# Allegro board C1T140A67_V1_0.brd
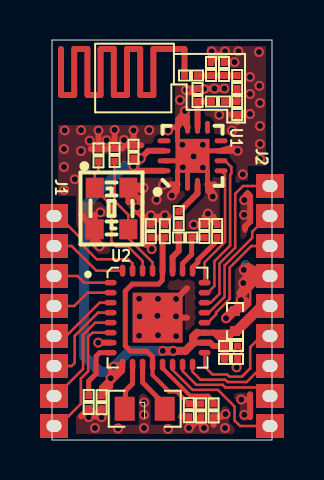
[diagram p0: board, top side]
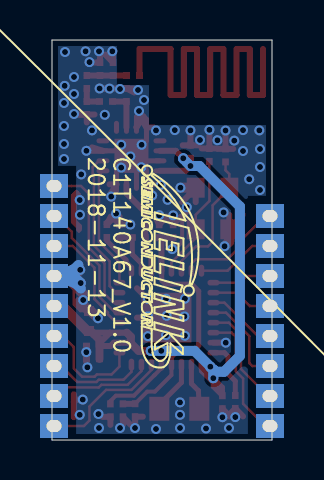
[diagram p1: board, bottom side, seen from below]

Outline 11 x 20 mm; copper layers: TOP, BOTTOM. Coordinates in mm from the lower left corner of the outline.
Outline path: 0,20 11,20 11,0 0,0 0,20

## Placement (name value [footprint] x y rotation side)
C1  1uF  [0201]  4.08 14.41 90 top
C2  NC  [0201]  3.13 14.25 270 top
C3  NC  [0201]  2.32 14.23 270 top
C4  0.1uF  [0201]  4.94 10.44 270 top
C5  2.2uF  [0201]  5.64 10.44 270 top
C6  2.7pF  [0201]  7.28 17.25 270 top
C7  2pF  [0201]  9.26 16.6 90 top
C8  1pF  [0201]  8.6 18.55 270 top
C9  NC  [0201]  7.95 18.55 270 top
C10  220pF  [0201]  6.34 11.09 90 top
C13  18pF  [0201]  7.62 10.45 90 top
C14  1uF  [0201]  8.26 10.45 90 top
C15  1uF  [0201]  1.84 1.9 90 top
C16  1uF  [0201]  8.95 4.7 0 top
C17  0.1uF  [0201]  8.95 4.05 0 top
C18  10uF  [0402]  9.15 5.95 90 top
C19  1uF  [0201]  2.48 1.89 270 top
C20  0.1uF  [0201]  6.84 1.49 270 top
C21  1uF  [0201]  7.45 1.48 270 top
C22  1uF  [0201]  8.08 1.48 270 top
J1  HEADER 8  [HDR_1P5_1X8]  0 11.2 270 top
J2  HEADER 9  [HDR_1P5_1X9]  11 12.7 90 top
L2  3.3nH  [0201]  8.3 16.93 0 top
L3  3.3nH  [0201]  9.26 17.9 90 top
L4  000R  [0201]  6.95 18.23 180 top
L5  1.3nH  [0201]  6.66 10.13 180 top
L6  47uH  [0805L]  4.64 1.56 180 top
U1  KCT8204L  [QFN_3X3_16PIN_0P5_1P70X1P70]  7.03 14.21 90 top
U2  TLSR8258F512ET32  [QFN_5X5_32PIN_0P5_2P50X2P50]  5.28 6.12 0 top
Y1  24MHz-12pF-+/-20ppm  [OSCCC200X250X080]  2.98 11.58 0 top

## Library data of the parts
C1 C4 C5 C16 C17 C19-C22 = C1005X5R1C104K: User Part Number: pn; Tolerance: RichardLC
C2 C3 = C1005_NC: User Part Number: pn; Tolerance: RichardLC
C6-C9 = C1005C0G1H020C: User Part Number: pn; Tolerance: RichardLC
C10 = C1608_NC: User Part Number: pn; Tolerance: RichardLC
C13 = C1005C0G1H100D: User Part Number: pn; Tolerance: RichardLC
C14 = C1608X5R1C105M: User Part Number: pn; Tolerance: RichardLC
C15 = C1005X5R1C105K: User Part Number: pn; Tolerance: RichardLC
C18 = C1608X5R0J106M
J1 = HEADER 8
J2 = HEADER 9
L2-L4 = MLK1005S3N3ST: User Part Number: pn; Tolerance: RichardLC
L5 = MLK1608_000R: User Part Number: pn; Tolerance: RichardLC
L6 = IND_0
U1 = KCT8204L
U2 = TLSR8258F512ET32
Y1 = CRYSTAL4/SM_0

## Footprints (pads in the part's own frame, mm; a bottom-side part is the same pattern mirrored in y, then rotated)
0201
  rect 0.35x0.33 smd: 1(-0.325,0) 2(0.325,0)
0402
  rect 0.5x0.5 smd: 1(-0.5,0) 2(0.5,0)
0805L
  rect 1x1.2 smd: 1(-1,0) 2(1,0)
HDR_1P5_1X8
  rect 1.2x1.4 hole 0.6x0.75: 1(0,0.1) 2(1.5,0.1) 3(3,0.1) 4(4.5,0.1) 5(6,0.1) 6(7.5,0.1) 7(9,0.1) 8(10.5,0.1)
HDR_1P5_1X9
  rect 1.2x1.4 hole 0.6x0.75: 1(0,0.1) 2(-1.5,0.1) 3(-3,0.1) 4(-4.5,0.1) 5(-6,0.1) 6(-7.5,0.1) 7(-9,0.1) 8(-10.5,0.1) 9(-12,0.1)
OSCCC200X250X080
  rect 0.9x1 smd: 1(-0.84,1.04) 2(-0.84,-1.04) 3(0.84,-1.04) 4(0.84,1.04)
QFN_3X3_16PIN_0P5_1P70X1P70
  oval 0.65x0.25 smd: 1(-1.425,0.75) 2(-1.425,0.25) 3(-1.425,-0.25) 4(-1.425,-0.75) 9(1.425,-0.75) 10(1.425,-0.25) 11(1.425,0.25) 12(1.425,0.75)
  oval 0.25x0.65 smd: 5(-0.75,-1.425) 6(-0.25,-1.425) 7(0.25,-1.425) 8(0.75,-1.425) 13(0.75,1.425) 14(0.25,1.425) 15(-0.25,1.425) 16(-0.75,1.425)
  rect 1.7x1.7 smd: 17(0,0)
QFN_5X5_32PIN_0P5_2P50X2P50
  oval 0.6x0.28 smd: 1(-2.35,1.75) 2(-2.35,1.25) 3(-2.35,0.75) 4(-2.35,0.25) 5(-2.35,-0.25) 6(-2.35,-0.75) 7(-2.35,-1.25) 8(-2.35,-1.75) 17(2.35,-1.75) 18(2.35,-1.25) 19(2.35,-0.75) 20(2.35,-0.25) 21(2.35,0.25) 22(2.35,0.75) 23(2.35,1.25) 24(2.35,1.75)
  oval 0.28x0.6 smd: 9(-1.75,-2.35) 10(-1.25,-2.35) 11(-0.75,-2.35) 12(-0.25,-2.35) 13(0.25,-2.35) 14(0.75,-2.35) 15(1.25,-2.35) 16(1.75,-2.35) 25(1.75,2.35) 26(1.25,2.35) 27(0.75,2.35) 28(0.25,2.35) 29(-0.25,2.35) 30(-0.75,2.35) 31(-1.25,2.35) 32(-1.75,2.35)
  rect 2.5x2.5 smd: 33(0,0)

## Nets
GND: C1.2 C2.1 C3.1 C4.1 C5.1 C6.1 C7.1 C8.1 C9.1 C13.2 C14.2 C15.1 C16.2 C17.2 C18.2 C19.2 C20.2 C21.2 C22.2 J2.4 U1.1(BYPASS) U1.2(GND#2) U1.4(GND#4) U1.7(GND#7) U1.11(ANT_SEL) U1.12(GND#12) U1.15(GND#15) U1.17(GND#17) U2.7(DVSS) U2.33(GND) Y1.2 Y1.4
PAVDD: C1.1 C16.1 C17.1 C18.1 C19.1 J2.5 U1.14(VDD#14) U1.16(VDD#16) U2.9(VDD_IO) U2.18(VDD3) U2.19(VDDIO_AMS)
TL_B4: J2.9 U2.14(SDMP0/P4/B[4])
TL_B5: J2.8 U2.15(SDMN0/P5/B[5])
TL_B6: J2.7 U2.16(SDMP1/DI/URTS/B[6])
TL_C0: J2.3 U2.20(I2C_SDA/P4N/URTS/C[0])
TL_C1: J2.2 U2.21(I2C_SCK/P1N/P0/C[1])
TL_C2: J2.1 U2.22(P0/7816_TRX/I2C_SDA/32KOUT/C[2])
TL_C3: U1.6(RX_EN) U2.23(P1/URX/I2C_SCK/32KIN/C[3])
TL_C4: U1.5(TX_EN) U2.24(P2/UCTS/P0N/BIAS/C[4])
TL_GPIO0: J1.3 U2.1(SWM/I2S_SDO/P2N/D[4])
TL_GPIO1: J1.2 U2.32(P1N/I2S_SDI/7816_TRX/D[3])
TL_GPIO2: J1.1 U2.31(CN/I2S_LR/P3/D[2])
TL_GRANT: J1.4 U2.2(CK/I2S_BCK/7816_TRX/D[7])
TL_PRIORITY: J1.5 U2.3(DMIC_DI/P0N/URX/A[0])
TL_REQUEST: J1.6 U2.4(DMIC_CLK/7816_CLK/I2S_CLK/A[1])
TL_SWS: J1.7 U2.5(SWS/URTS/A[7])
TL_URX: J2.6 U2.17(SDMN1/DO/URX/B[7])
TL_UTX: J1.8 U2.6(P4/UTX/ATSEL2/B[1])
TL_VDD_1V2: C4.2 C5.2 C20.1 C21.1 U2.12(VDD1V2) U2.28(AVDD1V2)
TL_XC1: C2.2 U2.29(XC1) Y1.3
TL_XC2: C3.2 U2.30(XC2) Y1.1
N19743728: C15.2 U2.8(VDD1V)
N19743785: L6.1 U2.11(VDCDC)
N19743791: L6.2 U2.10(VDCDC_SW)
N19743805: C22.1 U2.13(VDD_F)
N19743930: C10.1 L5.2 U2.27(ANT)
N19743949: C13.1 L5.1 U2.26(VANT)
N19743951: C14.1 U2.25(RESETB)
N19744088: C8.2 C9.2 L3.2 L4.1
N19744116: C7.2 L2.2 L3.1
N19750217: C6.2 L2.1 U1.10(ANT1)
N19756722: C10.2 U1.3(TXRX)

Pads without a net: L4 2; U1 8 9 13

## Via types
v1: diameter 0.5, hole 0.3, TOP to BOTTOM, 94 vias

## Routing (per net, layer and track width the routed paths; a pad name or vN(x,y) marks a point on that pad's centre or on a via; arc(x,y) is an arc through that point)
GND: length 74.5
  TOP w0.127: C18.2 9.58,6.45 9.91,6.77 9.91,8.58 9.78,8.71 ; 9.85,12.38 9.91,12.32 9.9,10.92 ; 9.85,12.38 9.78,12.45 9.71,12.38 ; 9.85,12.38 9.71,12.38 ; v1(9.61,12) 9.61,12.28 9.71,12.38 ; 9.65,10.41 9.65,10.54
  TOP w0.2: v1(4.99,9.54) 4.82,9.71 4.68,9.71 4.49,9.9 4.49,11.13 4.26,11.36 v1(4.26,11.64)
  TOP w0.25: 6.78,13.96 U1.2 ; 6.78,13.96 U1.15 ; 6.78,13.96 6.28,13.46 U1.1 6.28,12.45 6.05,12.23 v1(5.99,12.23) ; 6.78,13.96 U1.17 ; U1.17 6.28,14.96 U1.12 6.28,16.04 6.59,16.35 6.78,16.16 U1.11 ; U1.17 7.78,13.46 U1.4 7.78,12.45 8.04,12.19 v1(8.04,12.17) ; U1.17 7.28,14.46 U1.7
  TOP w0.3: 4.49,11.89 Y1.4 3.82,11.89 ; 6.43,16.18 U1.11 6.6,16.18 ; 9.78,8.71 J2.4 9.78,7.69 ; 9.75,16.27 9.32,16.27 ; 7.07,0.76 C21.2 7.45,0.76 ; v1(7.8,11.32) 7.8,11.32 8.26,10.86 C14.2 ; C1.2 v1(4.08,15.48) ; C1.2 4.46,14.74 ; C1.2 3.69,14.74 ; 7.87,11.17 C14.2 ; C14.2 8.06,11.17 ; 1.46,11.26 Y1.2 2.14,11.26 ; C3.1 2.71,14.56 ; C3.1 1.94,14.56 ; C3.1 v1(2.32,15.48) ; v1(9.23,3.63) 9.28,3.68 C17.2 9.28,4.38 v1(9.29,4.39) 9.28,4.4 9.28,4.7 ; 9.78,12.32 9.9,12.19 9.9,10.92 9.65,10.67 9.65,10.54 ; 8.12,12.78 U1.4 8.12,12.24 ; 8.08,0.76 C22.2 8.47,1.16 ; C15.1 2.22,1.18 ; C15.1 1.45,1.18 ; C15.1 v1(1.84,1.15) ; C2.1 v1(3.13,15.51) ; C2.1 3.52,14.58 ; C2.1 2.74,14.58 ; 6.89,17.57 C6.1 6.89,17.38 ; 9.26,16.27 9.65,16.27 ; 9.26,16.27 9.26,15.88 ; 9.26,16.27 8.87,16.27 ; 8.6,19.27 C8.1 8.99,18.88 ; 9.91,1.14 9.91,1.91 ; 9.91,1.91 9.91,2.29 ; 9.91,1.91 9.79,2.02 v1(9.46,2.02) ; 9,14.46 U1.7 9,14.63 ; 9.62,6.69 C18.2 9.39,6.92 ; 8.34,19.27 C9.1 7.95,19.27 ; 6.75,7.59 U2.33 6.75,6.12 ; v1(7.6,17.55) 7.62,17.57 8.28,17.57 8.3,17.55 8.32,17.57 8.6,17.57 ; 5.93,12.24 U1.1 5.93,12.78 ; 2.29,1.17 C19.2 ; C19.2 v1(2.48,1.14) ; C19.2 2.09,1.17 ; U2.7 v1(2.31,4.87) ; 5.93,15.63 U1.12 6.62,16.18 ; C5.1 5.83,11.16 ; C5.1 v1(5.64,11.24) ; C5.1 5.25,11.16 ; C4.1 5.33,11.16 ; C4.1 4.55,11.16 ; C4.1 v1(4.94,11.23) ; C13.2 v1(7.09,10.77) ; C13.2 8.01,11.17 ; C13.2 7.62,11.17 ; 6.46,1.16 C20.2 6.84,0.77
  TOP w0.5: 9.91,8.2 9.9,8.2 v1(9.59,8.51) ; 9.91,8.2 v1(9.56,7.85) ; 9.91,8.2 10.34,8.2 ; v1(8.7,6.09) 9.06,6.45 C18.2 9.62,6.92 ; v1(2.37,9.69) 2.14,9.92 Y1.2 ; Y1.4 v1(4.58,12.62) ; 10.34,8.2 9.48,7.34 ; 10.34,8.2 J2.4
  BOTTOM w0.3: 9.78,8.71 J2.4 9.78,7.69
  BOTTOM w0.5: 10.23,8.2 9.68,8.75 ; 10.23,8.2 J2.4 ; 10.23,8.2 10.18,8.2 ; 10.18,8.2 9.56,7.57 ; 10.18,8.2 9.91,8.2 v1(9.56,7.85)
  vias: v1(0.63,15.48) v1(0.6,14.55) v1(0.6,13.65) v1(0.6,12.5) v1(1.14,13.04) v1(1.45,15.49) v1(1.45,14.45) v1(1.89,14.97) v1(2.15,0.6) v1(2.42,11.38) v1(2.73,14.99) v1(3.3,0.58) v1(3.6,15) v1(4.36,7.06) v1(4.38,6.18) v1(4.35,5.21) v1(4.6,1.88) v1(4.6,1.26) v1(4.6,0.6) v1(4.86,15.49) v1(5.22,12.01) v1(5.3,7.06) v1(5.27,6.21) v1(5.3,5.24) v1(5.56,12.76) v1(5.8,15.48) v1(5.8,0.55) v1(6.2,7.05) v1(6.2,6.18) v1(6.21,5.19) v1(6.4,17) v1(6.52,14.76) v1(6.54,13.64) v1(6.7,17.5) v1(6.65,16.45) v1(6.85,0.6) v1(7.08,14.18) v1(7.54,14.76) v1(7.54,13.62) v1(7.6,0.6) v1(7.98,19.44) v1(8.12,17.57) v1(8.36,16.26) v1(8.62,17.58) v1(8.65,19.44) v1(8.68,1.3) v1(8.65,0.6) v1(9,15.48) v1(9.13,18.89) v1(9.32,19.44) v1(9.28,14.46) v1(9.44,7) v1(9.54,13.28) v1(9.6,11.26) v1(9.61,1.26) v1(9.9,18.15) v1(9.9,17.3) v1(9.9,16.3) v1(10.35,19.4) v1(10.37,17.71) v1(10.4,16.85) v1(10.4,15.7) v1(10.4,14.8) v1(10.4,14.05)
Net_38: length 25.9
  TOP w0.3: 0.45,19.55 0.45,17.25 1.11,17.25 1.11,19.55 1.77,19.55 1.77,17.25 2.43,17.25 2.43,19.55 3.09,19.55 3.09,17.25 3.75,17.25 3.75,19.55 4.41,19.55 4.41,17.25 5.07,17.25 5.07,19.55 6.62,19.55 6.62,18.23
PAVDD: length 37.5
  TOP w0.25: 3.53,3.68 3.08,3.24 ; 3.53,3.68 U2.9 3.18,3.77 v1(3.08,3.67) ; 3.53,3.68 3.53,3.45 2.48,2.4 ; 3.08,3.24 v1(3.08,3.67) ; 3.08,3.24 v1(2.94,3.09) ; v1(2.94,3.09) 2.48,2.63 2.48,2.4 ; v1(2.94,3.09) 2.94,3.52 v1(3.08,3.67) ; v1(2.94,3.09) 2.94,2.67 C19.1 2.48,2.4
  TOP w0.3: 8.1,5.37 8.86,5.37 8.92,5.3 ; 8.1,5.37 U2.19 7.26,5.37 ; 8.1,5.37 8.62,4.84 C16.1 8.07,4.7 7.91,4.87 U2.18 7.08,4.87 7.06,4.84 ; U1.14 4.81,14.46 v1(4.44,14.09) C1.1 v1(4.08,13.7) 4.32,13.46 U1.16
  TOP w0.4: v1(5.54,4.46) v1(6.06,4.46) 6.67,4.46 7.06,4.84 7.06,5.17 7.26,5.37 ; 8.62,4.84 8.63,4.84 8.63,5.01 9.07,5.45 C18.1 ; C17.1 8.63,4.7 C16.1
  TOP w0.5: C18.1 9.24,5.45 10.49,6.7 J2.5
  BOTTOM w0.5: v1(2.94,3.09) 2.94,3.54 2.85,3.45 ; v1(6.06,4.46) v1(5.54,4.46) 3.87,4.46 v1(3.08,3.67) 3.08,3.64 2.85,3.41 ; 2.85,3.41 2.85,3.45 ; 2.85,3.41 2.81,3.41 ; 2.85,3.45 2.81,3.41 ; 2.81,3.41 2.4,3.41 1.61,4.2 1.61,11.68 3.63,13.7 v1(4.08,13.7) 4.44,14.06 v1(4.44,14.09)
TL_B4: length 6.7
  TOP w0.127: U2.14 6.03,3.5 7.02,2.51 8.29,2.51 9.13,1.68 9.13,0.98 9.4,0.7 J2.9
TL_B5: length 5.2
  TOP w0.127: U2.15 6.53,3.45 7.22,2.76 8.53,2.76 8.66,2.63 10.47,2.63 J2.8
TL_B6: length 4.8
  TOP w0.127: U2.16 7.03,3.41 7.42,3.02 8.66,3.02 8.78,2.9 9.74,2.9 10.54,3.7 J2.7
TL_C0: length 5.8
  TOP w0.127: J2.3 9.96,9.7 8.88,8.62 8.88,7.06 8.88,7.05 8.87,7.04 8.2,6.37 8.2,6.28 7.79,5.87 U2.20
TL_C1: length 6.4
  TOP w0.127: U2.21 7.84,6.37 8.63,7.15 8.63,8.72 10.01,10.11 10.01,10.41 10.8,11.2 J2.2
TL_C2: length 8.2
  TOP w0.127: U2.22 7.93,6.87 8.37,7.31 8.37,8.83 9.16,9.61 9.16,12.31 9.55,12.7 9.79,12.7 10.01,12.7 J2.1
TL_C3: length 7.6
  TOP w0.127: U1.6 8.65,13.96 8.97,13.64 8.97,13.33 8.91,13.27 8.91,9.72 8.12,8.93 8.12,7.7 7.79,7.37 U2.23
TL_C4: length 6.1
  TOP w0.127: U2.24 7.63,8.89 8.65,9.91 8.65,13.26 U1.5
TL_GPIO0: length 3
  TOP w0.127: J1.3 1.27,8.2 1.6,7.87 U2.1
TL_GPIO1: length 3.9
  TOP w0.127: U2.32 2.22,8.47 0.98,9.7 J1.2
TL_GPIO2: length 5.4
  TOP w0.127: U2.31 4.03,8.82 3.81,9.04 2.23,9.04 1.42,9.85 1.42,10.11 0.33,11.2 J1.1
TL_GRANT: length 3.1
  TOP w0.127: J1.4 1.11,6.7 1.78,7.37 U2.2
TL_PRIORITY: length 3.5
  TOP w0.127: U2.3 2.38,6.87 0.71,5.2 J1.5
TL_REQUEST: length 4.7
  TOP w0.127: J1.6 0.98,3.7 1.13,3.85 1.13,5.2 2.3,6.37 U2.4
TL_SWS: length 5.3
  TOP w0.127: U2.5 2.16,5.87 1.55,5.26 1.55,3.55 0.2,2.2 J1.7
TL_URX: length 5.6
  TOP w0.127: J2.6 10.47,5.2 9.95,4.68 9.94,4.67 9.92,4.65 9.91,4.64 9.91,4.63 9.91,3.58 9.5,3.17 8.87,3.17 8.76,3.28 8.02,3.28 7.63,3.67 U2.17
TL_UTX: length 6.5
  TOP w0.127: U2.6 2.02,5.37 1.81,5.16 1.81,3.44 1.44,3.07 1.44,1.81 0.34,0.7 J1.8
TL_VDD_1V2: length 13.2
  TOP w0.2: U2.12 5.03,3.25 5.86,2.42 6.24,2.42 C20.1
  TOP w0.25: U2.12 5.03,4.15 4.74,4.44 3.94,4.44 3.66,4.71 3.66,7.44 4.01,7.79 5.33,7.79 5.52,7.98 5.52,8.45 U2.28
  TOP w0.3: C21.1 6.85,1.81 C20.1 ; U2.28 5.53,10 C5.2 C4.2
TL_XC1: length 6.2
  TOP w0.127: C2.2 3.13,11.95 3.82,11.26 Y1.3 3.82,10.09 5.03,8.88 U2.29
TL_XC2: length 6.9
  TOP w0.127: U2.30 4.53,8.95 3.8,9.68 3.2,9.68 2.97,9.91 2.97,11.73 2.14,12.57 Y1.1 2.14,13.3 2.32,13.49 C3.2
N19743728: length 2.9
  TOP w0.25: C15.2 1.84,2.95 2.21,3.32 2.21,4.19 2.38,4.37 U2.8
N19743785: length 2.7
  TOP w0.25: U2.11 4.53,2.88 5.68,1.72 L6.1
N19743791: length 2.3
  TOP w0.25: L6.2 3.68,2.47 4.03,2.82 U2.10
N19743805: length 3.6
  TOP w0.2: C22.1 8.08,1.95 7.81,2.22 6.9,2.22 5.88,3.24 5.88,3.24 5.53,3.59 U2.13
N19743930: length 2.4
  TOP w0.3: U2.27 6.03,9.15 6.33,9.45 L5.2 6.33,10.76 C10.1
N19743949: length 2.5
  TOP w0.25: U2.26 6.53,8.82 6.98,9.28 L5.1 7.62,10.13 C13.1
N19743951: length 2.2
  TOP w0.25: C14.1 8.26,9.96 7.3,9.01 7.3,8.9 7.03,8.63 U2.25
N19744088: length 2
  TOP w0.3: L4.1 C9.2 C8.2 L3.2
N19744116: length 1.3
  TOP w0.3: L3.1 C7.2 L2.2
N19750217: length 2
  TOP w0.3: U1.10 C6.2 L2.1
N19756722: length 1.8
  TOP w0.3: U1.3 7.28,12.33 6.36,11.42 C10.2

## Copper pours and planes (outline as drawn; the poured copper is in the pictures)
GND on TOP: 0.3,0.3 0.3,15.75 6.15,15.75 6.15,17.75 7.75,17.75 7.75,19.7 10.7,19.7 10.7,0.3 ; 1 cut-out
GND on BOTTOM: 0.3,0.3 0.3,15.75 6.15,15.75 6.15,17.75 7.76,17.75 7.76,19.7 10.7,19.7 10.7,0.3

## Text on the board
Ref Des/Silkscreen Bottom: C1T140A67_V1.0 | 2018-11-13
COMPVAL_TYPE_TOP: C1T140A67_V1.0 | 2018-11-13
User.7: FIGURE | SIZE | 0.3 | 0.75x0.6 | DRILL CHART: TOP to BOTTOM | ALL UNITS ARE IN MILLIMETERS | PLATED | QTY | 94 | 17
